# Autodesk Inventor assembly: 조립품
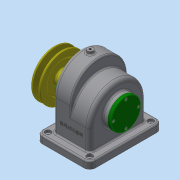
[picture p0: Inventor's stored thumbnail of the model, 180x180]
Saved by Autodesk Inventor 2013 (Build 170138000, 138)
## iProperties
Created: 2017-11
Part Number: 조립품
Document SubType Name: Assembly
Designer: dgall
Author: dgall
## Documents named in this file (14)
- C:\Users\dgall\Desktop\471007V1009\조립품.iam
- C:\Users\dgall\Desktop\471007V1009\본체.ipt
- C:\Users\dgall\Desktop\471007V1009\뒤커버.ipt
- C:\Users\dgall\Desktop\471007V1009\앞커버.ipt
- C:\Users\dgall\Desktop\471007V1009\베어링 6002.ipt
- C:\Users\dgall\Desktop\471007V1009\축.ipt
- C:\Users\dgall\Desktop\471007V1009\키 - 6 x 6 x 22.ipt
- C:\Users\dgall\Desktop\471007V1009\스퍼기어.ipt
- C:\Users\dgall\Desktop\471007V1009\오일 실 15 30 7.ipt
- C:\Users\dgall\Desktop\471007V1009\볼트 M3 x 8.ipt
- C:\Users\dgall\Desktop\471007V1009\V-벨트풀리.ipt
- C:\Users\dgall\Desktop\471007V1009\멈춤나사 - M4 x 10.ipt
- 멈춤나사 - M4 x 10.ipt
- C:\Users\dgall\Desktop\471007V1009\키 - 5 x 5 x 18.ipt
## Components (1 placed, 1 different names)
1. V-벨트풀리:1
